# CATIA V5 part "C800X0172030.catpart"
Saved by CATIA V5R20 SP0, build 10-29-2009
Part number: C800X0172030
Source: Unknown
Property "A": "30"
Property "ARTICLENO": "C800X0172030"
Property "B": "13"
Property "BOMINFO": "C800X0172030"
Property "C": "46"
Property "CA": "C800X0172030"
Property "D1": "38"
Property "DES": "ROTATING EYEBOLT WITH RING Ton 1,7 M20x30"
Property "E": "50"
Property "H": "105"
Property "L": "30"
Property "LINA": "C800X0172030"
Property "NB": "C800X0172030"
Property "NBSYN": "$CODE."
Property "NN": "C800X"
Property "NT": "Rotating eyebolt with ring"
Property "SIZE": "M20"
Property "SUPPLIER": "CF"
Property "SW": "30"
Property "WEIGHT": "530"
Property "WLL": "1.70"
Bounding box of the stored display mesh (mm): x -27.837 to 27.837, y -30 to 117.837, z -19 to 19
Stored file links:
  C:\Users\Utente\Desktop\3D files 800X\C800X0172030.catpart

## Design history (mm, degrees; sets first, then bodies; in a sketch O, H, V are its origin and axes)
Body1 "Geometry.1" (main body)
  Solid1 "C800X0172030.catpart": solid without history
